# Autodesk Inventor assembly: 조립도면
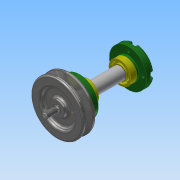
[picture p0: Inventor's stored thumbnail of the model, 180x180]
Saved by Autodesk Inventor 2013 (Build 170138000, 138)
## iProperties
Created: 2017-02
Part Number: 조립도면
Document SubType Name: Assembly
Designer: Administrator
Author: Administrator
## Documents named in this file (9)
- C:\Users\Administrator\Desktop\470207V1023\조립도면.iam
- C:\Users\Administrator\Desktop\470207V1023\1.본체.ipt
- C:\Users\Administrator\Desktop\470207V1023\뒤커버.ipt
- C:\Users\Administrator\Desktop\470207V1023\앞커버.ipt
- C:\Users\Administrator\Desktop\470207V1023\베어링 15 x 32 x 9.ipt
- C:\Users\Administrator\Desktop\470207V1023\축.ipt
- C:\Users\Administrator\Desktop\470207V1023\오일 실 15 25 7.ipt
- C:\Users\Administrator\Desktop\470207V1023\키 3 x 3 x 12.ipt
- C:\Users\Administrator\Desktop\470207V1023\V벨트풀리.ipt
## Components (4 placed, 3 different names)
1. 1.본체:1
2. KS B 2023 6002 - 15 x 32 x 9:1
3. KS B 2023 6002 - 15 x 32 x 9:2
4. V벨트풀리:1 — 각도:2
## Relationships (1: Angle 1)
- 각도:2 [Angle]: V벨트풀리:1
